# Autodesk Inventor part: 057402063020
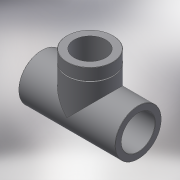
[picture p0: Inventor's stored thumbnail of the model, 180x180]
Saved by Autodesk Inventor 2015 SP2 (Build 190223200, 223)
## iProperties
Created: 2017-10
Part Number: 057402063020
Material: Generic
Description: PLASSON NOT ACTIVE- TEE THR-CEM REINF. P 63-2"
Document SubType Name: Modeling
Designer: KIM
Mass: 287.495 g
Surface Area: 786.954 cm^2
Volume: 287.495 cm^3
Density: 1 g/cm^3
Appearance: Default
Author: KIM
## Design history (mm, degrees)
derived "057402.ipt"
feature "Solid1::057402.ipt"
feature "Solid2::057402.ipt"
tag "TaggingFeature1"
body "Solid1"
other parameters: "d0" = 145, "d1" = 73, "d2" = 38, "d4" = 63, "d5" = 50.9904, "d7" = 0.56656, "d8" = 38, "d9" = 73, "d10" = 73, "d15" = 0, "d18" = 56.656, "d24" = 0.56656, "d30" = 56.656, "d31" = 26, "d32" = 0, "d33" = 50.9904, "d35" = 0, "d37" = 0.5, "d38" = 0.5, "d39" = 18.25, "d40" = 73, "G_" = 56.656, "E_" = 73, "H_" = 145, "lt_" = 26, "l_" = 38, "h_" = 73, "d_" = 63
